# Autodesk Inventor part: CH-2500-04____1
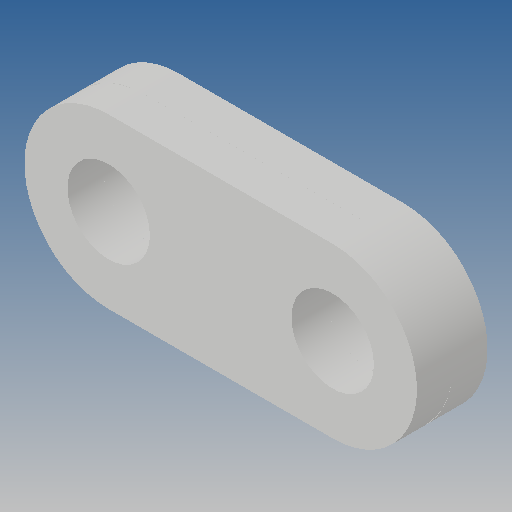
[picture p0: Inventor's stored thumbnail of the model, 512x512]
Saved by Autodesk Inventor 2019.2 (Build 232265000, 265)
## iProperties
Created: 2012-09
Part Number: CH-2500-04____1
Material: Ogólny
Document SubType Name: Modeling
Designer: CADENGINEERING4
Density: 1 g/cm^3
Appearance: Domyślna
Author: CADENGINEERING4
Revision Number: ÈÎºÎ
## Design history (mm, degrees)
feature "NONE" [ÊäÈë]
feature "ÊäÈë2"
node "Bryła1"
node "Bryła2"
